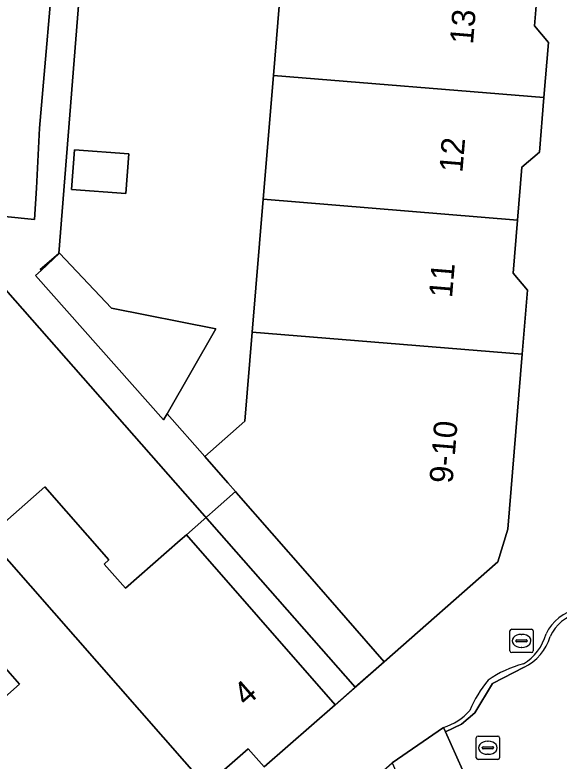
# Model space of a CAD drawing. Extents: x 159960 to 160866, y 382700 to 383354.
# Drawn here: x 160531.44 to 160554.77, y 383063.19 to 383095.2 of the extents above; entities that cross this region are included whole.
import ezdxf

# ---------------------------------------------------------------- set-up
doc = ezdxf.new("R2010")
doc.units = 0
for name, color, linetype in [('IMGEO_Erf', 7, 'Continuous'), ('IMGEO_Groenvoorziening', 7, 'Continuous'), ('IMGEO_Haag', 7, 'Continuous'), ('IMGEO_Kolk', 7, 'Continuous'), ('IMGEO_Muur', 7, 'Continuous'), ('IMGEO_Pand', 7, 'Continuous'), ('IMGEO_Pand_nummerreeks', 7, 'Continuous'), ('IMGEO_Pand_overbouw', 7, 'Continuous'), ('IMGEO_Rijbaan_lokaal_open', 7, 'Continuous'), ('IMGEO_Rioolput', 7, 'Continuous'), ('IMGEO_Voetpad_open', 7, 'Continuous')]:
    doc.layers.add(name, color=color, linetype=linetype)

msp = doc.modelspace()

# ---------------------------------------------------------------- linework, layer by layer
at = {"layer": 'IMGEO_Erf'}
for points in [[(160534.384, 383098.317), (160533.32, 383084.967), (160532.528, 383084.271), (160532.559, 383084.236), (160533.358, 383084.972), (160535.576, 383082.614), (160540.062, 383081.731), (160537.967, 383078.089), (160539.579, 383076.257), (160541.293, 383077.765), (160541.611, 383081.594), (160542.083, 383087.289), (160542.524, 383092.606), (160542.975, 383098.034)], [(160530.268, 383072.789), (160532.722, 383074.949), (160535.473, 383071.823), (160535.266, 383071.641), (160536.182, 383070.6), (160538.53, 383072.667), (160538.794, 383072.9), (160541.882, 383069.367), (160545.173, 383065.602), (160546.031, 383066.356), (160530.296, 383084.243)], [(160529.228, 383064.379), (160531.632, 383066.495), (160527.915, 383070.718)]]:
    msp.add_lwpolyline(points, dxfattribs=at)
msp.add_lwpolyline([(160533.99, 383089.409), (160536.325, 383089.232), (160536.196, 383087.532), (160533.861, 383087.709)], close=True, dxfattribs=at)
at = {"layer": 'IMGEO_Groenvoorziening'}
msp.add_lwpolyline([(160553.272, 383067.214), (160551.918, 383066.516), (160551.165, 383065.258), (160550.589, 383064.77), (160549.905, 383064.449), (160551.123, 383061.734), (160552.145, 383059.353), (160552.544, 383059.972), (160553.128, 383060.42), (160553.823, 383060.604), (160554.422, 383061.002), (160554.62, 383060.818), (160554.722, 383060.865)], dxfattribs=at)
for centre, radius, start, end in [((160555.982, 383067.827), 1.737, 102.5071, 155.9581), ((160552.336, 383069.149), 2.15, 295.8192, 343.3939)]:
    msp.add_arc(centre, radius, start, end, dxfattribs=at)
at = {"layer": 'IMGEO_Haag'}
msp.add_lwpolyline([(160549.819, 383064.636), (160549.905, 383064.449), (160550.589, 383064.77), (160551.165, 383065.258), (160551.918, 383066.516), (160553.272, 383067.214)], dxfattribs=at)
for centre, radius, start, end in [((160555.975, 383067.792), 1.96, 102.3534, 153.927), ((160555.982, 383067.827), 1.737, 102.5071, 155.9581), ((160552.118, 383069.21), 2.17, 301.2274, 345.1176), ((160552.336, 383069.149), 2.15, 295.8192, 343.3939), ((160554.298, 383063.072), 4.411, 103.8389, 125.5233), ((160555.924, 383063.214), 5.425, 140.5443, 156.7035), ((160549.12, 383066.95), 2.417, 286.7997, 318.8667)]:
    msp.add_arc(centre, radius, start, end, dxfattribs=at)
at = {"layer": 'IMGEO_Kolk'}
for p, q in [((160552.667, 383067.92), (160552.667, 383068.772)), ((160552.742, 383068.846), (160553.594, 383068.846)), ((160553.668, 383068.772), (160553.668, 383067.92)), ((160552.969, 383068.389), (160553.367, 383068.389)), ((160553.155, 383068.626), (160553.18, 383068.626)), ((160552.926, 383068.34), (160552.926, 383068.352)), ((160553.364, 383068.303), (160552.966, 383068.303)), ((160553.178, 383068.066), (160553.153, 383068.066)), ((160553.41, 383068.352), (160553.41, 383068.34)), ((160553.594, 383067.846), (160552.742, 383067.846))]:
    msp.add_line(p, q, dxfattribs=at)
for points in [[(160552.667, 383067.92), (160552.667, 383068.772)], [(160552.742, 383068.846), (160553.594, 383068.846)], [(160553.668, 383068.772), (160553.668, 383067.92)], [(160553.594, 383067.846), (160552.742, 383067.846)]]:
    msp.add_lwpolyline(points, dxfattribs=at)
for centre, radius, start, end in [((160552.744, 383068.77), 0.0765, 91.552, 178.448), ((160552.744, 383068.77), 0.0765, 91.552, 178.448), ((160553.592, 383068.77), 0.0765, 1.552, 88.448), ((160553.592, 383068.77), 0.0765, 1.552, 88.448), ((160552.966, 383068.349), 0.0403, 85.8775, 175.7526), ((160553.371, 383068.351), 0.0386, 1.7309, 96.639), ((160552.963, 383068.339), 0.0366, 178.938, 274.7102), ((160553.367, 383068.346), 0.043, 264.8664, 352.4533), ((160552.744, 383067.922), 0.0765, 181.552, 268.448), ((160552.744, 383067.922), 0.0765, 181.552, 268.448), ((160553.592, 383067.922), 0.0765, 271.552, 358.448), ((160553.592, 383067.922), 0.0765, 271.552, 358.448)]:
    msp.add_arc(centre, radius, start, end, dxfattribs=at)
for centre, major_axis, ratio, start_param, end_param in [((160553.154, 383068.346), (-0.387, 0.002), 0.722429, 4.712389, 7.853982), ((160553.179, 383068.346), (-0.39, 0.002), 0.717154, 1.570796, 4.712389)]:
    msp.add_ellipse(centre, major_axis=major_axis, ratio=ratio, start_param=start_param, end_param=end_param, dxfattribs=at)
at = {"layer": 'IMGEO_Muur'}
msp.add_lwpolyline([(160549.819, 383064.636), (160549.905, 383064.449), (160550.589, 383064.77), (160551.165, 383065.258), (160551.918, 383066.516), (160553.272, 383067.214)], dxfattribs=at)
for centre, radius, start, end in [((160555.975, 383067.792), 1.96, 102.3534, 153.927), ((160555.982, 383067.827), 1.737, 102.5071, 155.9581), ((160552.118, 383069.21), 2.17, 301.2274, 345.1176), ((160552.336, 383069.149), 2.15, 295.8192, 343.3939), ((160554.298, 383063.072), 4.411, 103.8389, 125.5233), ((160555.924, 383063.214), 5.425, 140.5443, 156.7035), ((160549.12, 383066.95), 2.417, 286.7997, 318.8667)]:
    msp.add_arc(centre, radius, start, end, dxfattribs=at)
at = {"layer": 'IMGEO_Pand'}
for points in [[(160533.195, 383098.415), (160533.72, 383104.491), (160533.962, 383107.284), (160534.122, 383109.141), (160534.186, 383109.88), (160533.198, 383111.163), (160488.491, 383114.709), (160487.777, 383114.015), (160502.502, 383074.84), (160503.326, 383075.15), (160504.293, 383075.514), (160506.667, 383076.407), (160508.186, 383072.366), (160520.336, 383076.937), (160522.091, 383078.518), (160531.012, 383086.555), (160532.285, 383086.423), (160532.358, 383087.767), (160532.496, 383090.334)], [(160542.975, 383098.034), (160542.524, 383092.606), (160554.123, 383091.66), (160554.319, 383094.017), (160553.715, 383094.73), (160553.916, 383097.142)], [(160542.524, 383092.606), (160542.083, 383087.289), (160552.991, 383086.4), (160553.179, 383088.673), (160553.928, 383089.307), (160554.123, 383091.66)], [(160533.861, 383087.709), (160536.196, 383087.532), (160536.325, 383089.232), (160533.99, 383089.409)], [(160541.611, 383081.594), (160553.196, 383080.65), (160553.423, 383083.392), (160552.802, 383084.126), (160552.991, 383086.4), (160542.083, 383087.289)], [(160532.559, 383084.236), (160532.328, 383084.023), (160537.814, 383077.822), (160537.967, 383078.089), (160540.062, 383081.731), (160535.576, 383082.614), (160533.358, 383084.972)], [(160553.196, 383080.65), (160541.611, 383081.594), (160541.293, 383077.765), (160539.579, 383076.257), (160540.571, 383075.122), (160540.896, 383074.75), (160540.926, 383074.716), (160543.985, 383071.216), (160547.275, 383067.451), (160552.152, 383071.743), (160552.572, 383073.133)], [(160539.632, 383062.132), (160541.437, 383063.72), (160542.131, 383062.942), (160545.173, 383065.602), (160541.882, 383069.367), (160538.794, 383072.9), (160538.53, 383072.667), (160536.182, 383070.6), (160535.266, 383071.641), (160535.473, 383071.823), (160532.722, 383074.949), (160530.268, 383072.789)], [(160539.632, 383062.132), (160530.268, 383072.789), (160527.915, 383070.718), (160531.632, 383066.495), (160529.228, 383064.379), (160534.867, 383057.942), (160535.348, 383058.365), (160535.948, 383058.162), (160537.465, 383059.497), (160537.34, 383060.115)]]:
    msp.add_lwpolyline(points, close=True, dxfattribs=at)
at = {"layer": 'IMGEO_Pand_overbouw'}
msp.add_lwpolyline([(160543.985, 383071.216), (160540.926, 383074.716), (160540.896, 383074.75), (160538.794, 383072.9), (160541.882, 383069.367), (160545.173, 383065.602), (160547.275, 383067.451)], close=True, dxfattribs=at)
at = {"layer": 'IMGEO_Rijbaan_lokaal_open'}
msp.add_lwpolyline([(160552.934, 383057.049), (160552.761, 383057.198), (160552.842, 383057.296), (160552.921, 383057.396), (160552.295, 383059.135), (160552.094, 383059.22), (160552.145, 383059.353), (160551.123, 383061.734), (160549.905, 383064.449), (160549.819, 383064.636), (160547.614, 383063.12), (160549.987, 383057.706), (160550.175, 383057.572), (160550.056, 383057.469), (160550.644, 383055.631), (160550.747, 383055.598), (160550.706, 383055.441)], dxfattribs=at)
at = {"layer": 'IMGEO_Rioolput'}
for p, q in [((160551.298, 383064.26), (160552.15, 383064.26)), ((160551.223, 383063.334), (160551.223, 383064.186)), ((160551.711, 383064.04), (160551.736, 383064.04)), ((160552.224, 383064.186), (160552.224, 383063.334)), ((160551.482, 383063.754), (160551.482, 383063.766)), ((160551.92, 383063.717), (160551.522, 383063.717)), ((160551.525, 383063.803), (160551.923, 383063.803)), ((160551.966, 383063.766), (160551.966, 383063.754)), ((160552.15, 383063.26), (160551.298, 383063.26)), ((160551.734, 383063.48), (160551.709, 383063.48))]:
    msp.add_line(p, q, dxfattribs=at)
for points in [[(160551.298, 383064.26), (160552.15, 383064.26)], [(160551.223, 383063.334), (160551.223, 383064.186)], [(160552.224, 383064.186), (160552.224, 383063.334)], [(160552.15, 383063.26), (160551.298, 383063.26)]]:
    msp.add_lwpolyline(points, dxfattribs=at)
for centre, radius, start, end in [((160551.3, 383064.184), 0.0765, 91.552, 178.448), ((160551.3, 383064.184), 0.0765, 91.552, 178.448), ((160552.148, 383064.184), 0.0765, 1.552, 88.448), ((160552.148, 383064.184), 0.0765, 1.552, 88.448), ((160551.522, 383063.763), 0.0403, 85.8775, 175.7526), ((160551.519, 383063.753), 0.0366, 178.938, 274.7102), ((160551.923, 383063.76), 0.043, 264.8664, 352.4533), ((160551.927, 383063.765), 0.0386, 1.7309, 96.639), ((160551.3, 383063.336), 0.0765, 181.552, 268.448), ((160551.3, 383063.336), 0.0765, 181.552, 268.448), ((160552.148, 383063.336), 0.0765, 271.552, 358.448), ((160552.148, 383063.336), 0.0765, 271.552, 358.448)]:
    msp.add_arc(centre, radius, start, end, dxfattribs=at)
for centre, major_axis, ratio, start_param, end_param in [((160551.71, 383063.76), (-0.387, 0.002), 0.722429, 4.712389, 7.853982), ((160551.735, 383063.76), (-0.39, 0.002), 0.717154, 1.570796, 4.712389)]:
    msp.add_ellipse(centre, major_axis=major_axis, ratio=ratio, start_param=start_param, end_param=end_param, dxfattribs=at)
at = {"layer": 'IMGEO_Voetpad_open'}
for points in [[(160533.195, 383098.415), (160532.496, 383090.334), (160532.358, 383087.767), (160532.285, 383086.423), (160531.012, 383086.555), (160522.091, 383078.518), (160520.336, 383076.937), (160508.186, 383072.366), (160506.667, 383076.407), (160504.293, 383075.514), (160503.326, 383075.15), (160502.502, 383074.84), (160487.777, 383114.015)], [(160530.296, 383084.243), (160546.031, 383066.356), (160547.275, 383067.451), (160543.985, 383071.216), (160540.926, 383074.716), (160540.896, 383074.75), (160540.571, 383075.122), (160539.579, 383076.257), (160537.967, 383078.089), (160537.814, 383077.822), (160532.328, 383084.023), (160532.559, 383084.236), (160532.528, 383084.271), (160533.32, 383084.967), (160534.384, 383098.317)], [(160553.916, 383097.142), (160553.715, 383094.73), (160554.319, 383094.017), (160554.123, 383091.66), (160553.928, 383089.307), (160553.179, 383088.673), (160552.991, 383086.4), (160552.802, 383084.126), (160553.423, 383083.392), (160553.196, 383080.65), (160552.572, 383073.133), (160552.152, 383071.743), (160547.275, 383067.451), (160546.031, 383066.356), (160545.173, 383065.602), (160542.131, 383062.942), (160541.437, 383063.72), (160539.632, 383062.132)], [(160532.081, 383049.37), (160533.771, 383050.874), (160537.937, 383054.599), (160542.574, 383058.683), (160545.337, 383061.117), (160547.614, 383063.12), (160549.819, 383064.636)]]:
    msp.add_lwpolyline(points, dxfattribs=at)
for centre, radius, start, end in [((160555.975, 383067.792), 1.96, 102.3534, 153.927), ((160552.118, 383069.21), 2.17, 301.2274, 345.1176), ((160554.298, 383063.072), 4.411, 103.8389, 125.5233), ((160555.924, 383063.214), 5.425, 140.5443, 156.7035), ((160549.12, 383066.95), 2.417, 286.7997, 318.8667)]:
    msp.add_arc(centre, radius, start, end, dxfattribs=at)

# ---------------------------------------------------------------- texts
at = {"layer": 'IMGEO_Pand_nummerreeks'}
for s, rotation, p in [('13', 85.2739, (160551.082, 383093.913)), ('12', 85.2739, (160550.628, 383088.416)), ('11', 85.2739, (160550.183, 383083.04)), ('9-10', 85.2561, (160550.205, 383075.077)), ('4', 41.1673, (160541.35, 383065.501))]:
    msp.add_text(s, height=1, rotation=rotation, dxfattribs=at).set_placement(p)

doc.saveas('drawing.dxf')
